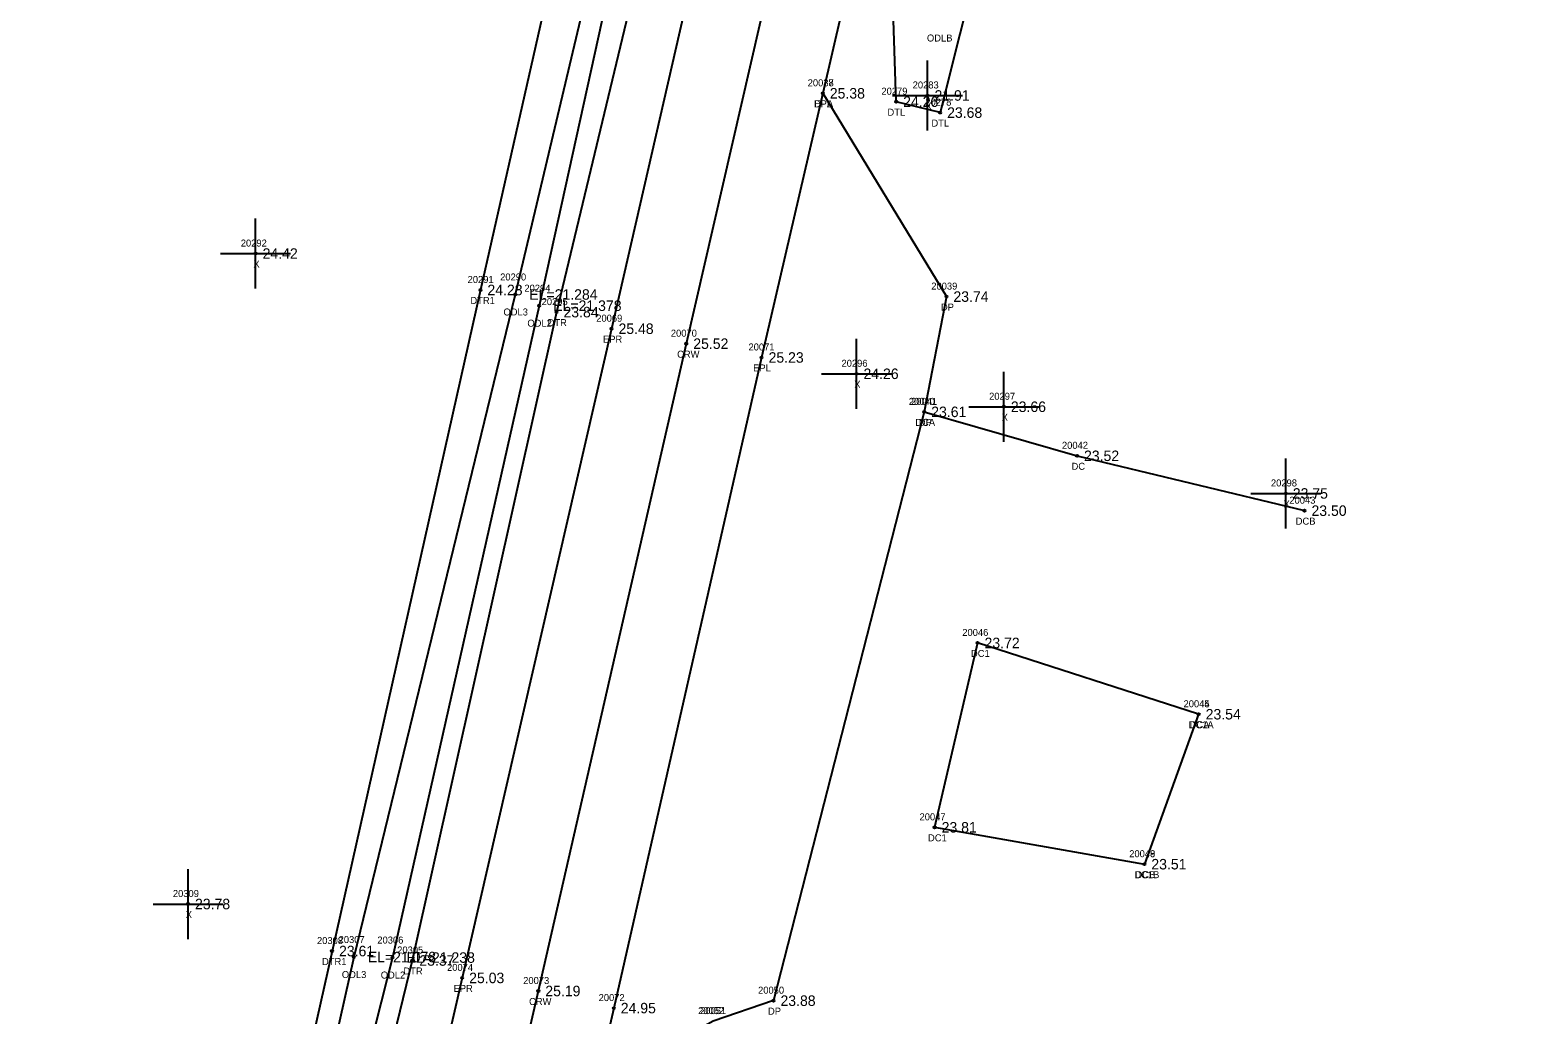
# Model space of a CAD drawing. Extents: x 2655177 to 2656219, y 761780 to 764748.
# Drawn here: x 2655847.5 to 2656062.9, y 764137.7 to 764278.4 of the extents above; entities that cross this region are included whole.
import ezdxf

# ---------------------------------------------------------------- set-up
doc = ezdxf.new("R2010")
doc.units = 0
for name, color, linetype in [('RD_DTM_BkLn1', 7, 'Continuous'), ('RD_EX_Conc', 7, 'Continuous'), ('RD_EX_Conc_txCode', 7, 'Continuous'), ('RD_EX_Driveway', 7, 'Continuous'), ('RD_EX_Driveway_txCode', 7, 'Continuous'), ('RD_EX_H2O', 7, 'Continuous'), ('RD_EX_H2O_txCode', 7, 'Continuous'), ('RD_EX_Misc', 7, 'Continuous'), ('RD_EX_Misc_txCode', 7, 'Continuous'), ('RD_EX_Road', 7, 'Continuous'), ('RD_EX_Road_txCode', 7, 'Continuous'), ('RD_EX_TX_Conc_ELEV', 7, 'Continuous'), ('RD_EX_TX_Driveway_ELEV', 7, 'Continuous'), ('RD_EX_TX_H2O_ELEV', 7, 'Continuous'), ('RD_EX_TX_Misc_ELEV', 7, 'Continuous'), ('RD_EX_TX_Road_ELEV', 7, 'Continuous'), ('RD_HC_Survey_ELEV', 7, 'Continuous'), ('RD_HC_Survey_txCode', 7, 'Continuous'), ('RD_SMD_Locator', 7, 'Continuous')]:
    doc.layers.add(name, color=color, linetype=linetype)

msp = doc.modelspace()

# ---------------------------------------------------------------- linework, layer by layer
at = {"layer": 'RD_DTM_BkLn1'}
msp.add_lwpolyline([(2656052.36, 764720.46), (2656029.22, 764619.66), (2656007.41, 764523.97), (2655985.61, 764427.64), (2655963.53, 764330.64), (2655941.2, 764233.56), (2655920.06, 764141.06), (2655898.52, 764047.86), (2655877.71, 763954.88), (2655855.89, 763859.81), (2655834.07, 763763.97), (2655811.81, 763666.79), (2655790.48, 763573.22), (2655769.27, 763483.63), (2655747.64, 763389.32), (2655725.4, 763293.96), (2655721.51, 763275.9)], dxfattribs=at)
at = {"layer": 'RD_EX_Conc'}
msp.add_line((2656014.41, 764180.61), (2656006.65, 764159.18), dxfattribs=at)
for points in [[(2655975.2, 764223.82), (2655997.03, 764217.54), (2656029.53, 764209.7)], [(2656014.41, 764180.61), (2655982.82, 764190.8), (2655976.69, 764164.45), (2656006.65, 764159.18)]]:
    msp.add_lwpolyline(points, dxfattribs=at)
at = {"layer": 'RD_EX_Driveway'}
msp.add_lwpolyline([(2655960.71, 764269.34), (2655978.37, 764240.29), (2655975.2, 764223.82), (2655953.66, 764139.68), (2655945.06, 764136.76), (2655937.53, 764132.52), (2655926.81, 764121.01)], dxfattribs=at)
at = {"layer": 'RD_EX_H2O'}
for points in [[(2655985.99, 764532.58), (2655990.84, 764527.53), (2655967.74, 764432.27), (2655946, 764335.4), (2655922.66, 764238.07), (2655902.06, 764145.42), (2655879.59, 764053.25), (2655859.1, 763959.14), (2655841.15, 763874.16), (2655837.57, 763865.39), (2655829.11, 763865.29), (2655761.29, 763886.78)], [(2655985.99, 764532.58), (2655980.45, 764530.42), (2655978.53, 764524.06), (2655957.73, 764434.81), (2655933.82, 764338.64), (2655911.79, 764241.24), (2655890.59, 764146.77), (2655869.91, 764054.39), (2655847.97, 763961.11)], [(2655986.13, 764527.03), (2655964.81, 764432.99), (2655941.76, 764337.09), (2655920.19, 764238.99), (2655899.24, 764145.84), (2655875.75, 764053.31), (2655856.78, 763959.16), (2655834.97, 763871.07)], [(2655983.66, 764527.79), (2655962.07, 764433.73), (2655939.64, 764337.32), (2655916.77, 764240.59), (2655893.69, 764145.91), (2655873.09, 764053.84), (2655852.96, 763960.1)], [(2656003.29, 764410.57), (2656005.26, 764401.05), (2655991.55, 764322.61), (2655977.47, 764266.58), (2655971.19, 764268.14), (2655970.76, 764281.2)]]:
    msp.add_lwpolyline(points, dxfattribs=at)
at = {"layer": 'RD_EX_Misc'}
for p, q in [((2655975.67, 764264.03), (2655975.67, 764274.03)), ((2655970.67, 764269.03), (2655980.67, 764269.03)), ((2655879.67, 764241.44), (2655879.67, 764251.44)), ((2655874.67, 764246.44), (2655884.67, 764246.44)), ((2655965.52, 764224.26), (2655965.52, 764234.26)), ((2655960.52, 764229.26), (2655970.52, 764229.26)), ((2655986.58, 764219.55), (2655986.58, 764229.55)), ((2655981.58, 764224.55), (2655991.58, 764224.55)), ((2656026.86, 764207.16), (2656026.86, 764217.16)), ((2656021.86, 764212.16), (2656031.86, 764212.16)), ((2655870.01, 764148.49), (2655870.01, 764158.49)), ((2655865.01, 764153.49), (2655875.01, 764153.49))]:
    msp.add_line(p, q, dxfattribs=at)
at = {"layer": 'RD_EX_Road'}
for points in [[(2656041.72, 764723.31), (2656018.5, 764622.03), (2656002.75, 764552.49), (2655997.43, 764530.02), (2655974.74, 764429.64), (2655952.97, 764333.57), (2655930.52, 764235.7), (2655909.18, 764142.93), (2655887.93, 764050.57), (2655866.91, 763957.26), (2655846.82, 763869.53), (2655845.21, 763862.22), (2655839.99, 763839.71), (2655823.38, 763766.66), (2655801.33, 763669.93), (2655780.03, 763576.53), (2655774.26, 763551.85), (2655771.37, 763539.86), (2655759.09, 763486.9), (2655736.94, 763391.72), (2655715.19, 763296.77), (2655711.35, 763278.45)], [(2656062.87, 764717.57), (2656039.84, 764617.04), (2656035.41, 764597.94), (2656033.38, 764589.18), (2656018.27, 764522.6), (2656017.22, 764517.64), (2656011.07, 764490.22), (2655996.52, 764425.63), (2655974.03, 764327.02), (2655960.71, 764269.34), (2655951.96, 764231.59), (2655930.84, 764138.62), (2655926.81, 764121.01)]]:
    msp.add_lwpolyline(points, dxfattribs=at)
at = {"layer": 'RD_SMD_Locator'}
for centre in [(2655960.71, 764269.34), (2655960.71, 764269.34), (2655971.19, 764268.14), (2655975.67, 764269.03), (2655977.47, 764266.58), (2655879.67, 764246.44), (2655911.79, 764241.24), (2655916.77, 764240.59), (2655978.37, 764240.29), (2655920.19, 764238.99), (2655922.66, 764238.07), (2655930.52, 764235.7), (2655941.2, 764233.56), (2655951.96, 764231.59), (2655965.52, 764229.26), (2655986.58, 764224.55), (2655975.2, 764223.82), (2655975.2, 764223.82), (2655997.03, 764217.54), (2656026.86, 764212.16), (2656029.53, 764209.7), (2655982.82, 764190.8), (2656014.41, 764180.61), (2656014.41, 764180.61), (2655976.69, 764164.45), (2656006.65, 764159.18), (2656006.65, 764159.18), (2655870.01, 764153.49), (2655890.59, 764146.77), (2655893.69, 764145.91), (2655899.24, 764145.84), (2655902.06, 764145.42), (2655909.18, 764142.93), (2655920.06, 764141.06), (2655930.84, 764138.62), (2655953.66, 764139.68)]:
    msp.add_circle(centre, 0.15, dxfattribs=at)

# ---------------------------------------------------------------- texts
at = {"layer": 'RD_EX_Conc_txCode'}
for s, p in [('20041', (2655973.32, 764224.82)), ('DCA', (2655973.93, 764221.82)), ('20042', (2655994.88, 764218.54)), ('DC', (2655996.25, 764215.54)), ('20043', (2656027.37, 764210.7)), ('DCB', (2656028.28, 764207.7)), ('20046', (2655980.64, 764191.8)), ('DC1', (2655981.88, 764188.8)), ('20044', (2656012.25, 764181.61)), ('20045', (2656012.25, 764181.61)), ('DC1A', (2656012.98, 764178.61)), ('DCA', (2656013.14, 764178.61)), ('20047', (2655974.53, 764165.45)), ('DC1', (2655975.74, 764162.45)), ('20048', (2656004.49, 764160.18)), ('20049', (2656004.49, 764160.18)), ('DC1B', (2656005.23, 764157.18)), ('DCB', (2656005.39, 764157.18)), ('20052', (2655942.9, 764137.76))]:
    msp.add_text(s, height=1, dxfattribs=at).set_placement(p)
at = {"layer": 'RD_EX_Driveway_txCode'}
for s, p in [('20038', (2655958.55, 764270.34)), ('DPA', (2655959.44, 764267.34)), ('20039', (2655976.21, 764241.29)), ('DP', (2655977.59, 764238.29)), ('20040', (2655973, 764224.82)), ('DP', (2655974.42, 764221.82)), ('20050', (2655951.46, 764140.68)), ('20051', (2655943.18, 764137.76)), ('DP', (2655952.88, 764137.68))]:
    msp.add_text(s, height=1, dxfattribs=at).set_placement(p)
at = {"layer": 'RD_EX_H2O_txCode'}
for s, p in [('ODLB', (2655975.59, 764276.74)), ('20279', (2655969.08, 764269.14)), ('20278', (2655975.36, 764267.58)), ('DTL', (2655969.95, 764266.14)), ('DTL', (2655976.23, 764264.58)), ('20291', (2655909.96, 764242.24)), ('20290', (2655914.61, 764242.59)), ('20294', (2655918.07, 764240.99)), ('DTR1', (2655910.36, 764239.24)), ('20295', (2655920.54, 764239.07)), ('ODL3', (2655915.08, 764237.59)), ('ODL2', (2655918.5, 764235.99)), ('DTR', (2655921.39, 764236.07)), ('20308', (2655888.44, 764147.77)), ('20307', (2655891.53, 764147.91)), ('20306', (2655897.06, 764147.84)), ('20305', (2655899.9, 764146.42)), ('DTR1', (2655889.16, 764144.77)), ('ODL3', (2655891.99, 764142.91)), ('ODL2', (2655897.55, 764142.84)), ('DTR', (2655900.79, 764143.42))]:
    msp.add_text(s, height=1, dxfattribs=at).set_placement(p)
at = {"layer": 'RD_EX_Misc_txCode'}
for s, p in [('20283', (2655973.55, 764270.03)), ('X', (2655975.36, 764267.03)), ('20292', (2655877.55, 764247.44)), ('X', (2655879.35, 764244.44)), ('20296', (2655963.38, 764230.26)), ('X', (2655965.2, 764227.26)), ('20297', (2655984.47, 764225.55)), ('X', (2655986.27, 764222.55)), ('20298', (2656024.74, 764213.16)), ('X', (2656026.54, 764210.16)), ('20309', (2655867.85, 764154.49)), ('X', (2655869.69, 764151.49))]:
    msp.add_text(s, height=1, dxfattribs=at).set_placement(p)
at = {"layer": 'RD_EX_Road_txCode'}
for s, p in [('20037', (2655958.55, 764270.34)), ('EPL', (2655959.51, 764267.34)), ('20069', (2655928.34, 764236.7)), ('EPR', (2655929.3, 764233.7)), ('20071', (2655950.09, 764232.59)), ('EPL', (2655950.76, 764229.59)), ('20074', (2655907.02, 764143.93)), ('EPR', (2655907.95, 764140.93)), ('20072', (2655928.68, 764139.62))]:
    msp.add_text(s, height=1, dxfattribs=at).set_placement(p)
at = {"layer": 'RD_EX_TX_Conc_ELEV'}
for s, p in [('23.61', (2655976.2, 764223.07)), ('23.52', (2655998.03, 764216.79)), ('23.50', (2656030.53, 764208.95)), ('23.72', (2655983.82, 764190.05)), ('23.54', (2656015.41, 764179.86)), ('23.54', (2656015.41, 764179.86)), ('23.81', (2655977.69, 764163.7)), ('23.51', (2656007.65, 764158.43)), ('23.51', (2656007.65, 764158.43))]:
    msp.add_text(s, height=1.5, dxfattribs=at).set_placement(p)
at = {"layer": 'RD_EX_TX_Driveway_ELEV'}
for s, p in [('25.38', (2655961.71, 764268.59)), ('23.74', (2655979.37, 764239.54)), ('23.61', (2655976.2, 764223.07)), ('23.88', (2655954.66, 764138.93))]:
    msp.add_text(s, height=1.5, dxfattribs=at).set_placement(p)
at = {"layer": 'RD_EX_TX_H2O_ELEV'}
for s, p in [('24.26', (2655972.19, 764267.39)), ('23.68', (2655978.47, 764265.83)), ('24.28', (2655912.79, 764240.49)), ('EL=21.284', (2655918.77, 764239.84)), ('EL=21.378', (2655922.19, 764238.24)), ('23.84', (2655923.66, 764237.32)), ('23.61', (2655891.59, 764146.02)), ('EL=21.078', (2655895.69, 764145.16)), ('EL=21.238', (2655901.24, 764145.09)), ('23.37', (2655903.06, 764144.67))]:
    msp.add_text(s, height=1.5, dxfattribs=at).set_placement(p)
at = {"layer": 'RD_EX_TX_Misc_ELEV'}
for s, p in [('21.91', (2655976.67, 764268.28)), ('24.42', (2655880.67, 764245.69)), ('24.26', (2655966.52, 764228.51)), ('23.66', (2655987.58, 764223.8)), ('23.75', (2656027.86, 764211.41)), ('23.78', (2655871.01, 764152.74))]:
    msp.add_text(s, height=1.5, dxfattribs=at).set_placement(p)
at = {"layer": 'RD_EX_TX_Road_ELEV'}
for s, p in [('25.38', (2655961.71, 764268.59)), ('25.48', (2655931.52, 764234.95)), ('25.23', (2655952.96, 764230.84)), ('25.03', (2655910.18, 764142.18)), ('24.95', (2655931.84, 764137.87))]:
    msp.add_text(s, height=1.5, dxfattribs=at).set_placement(p)
at = {"layer": 'RD_HC_Survey_ELEV'}
for s, p in [('25.52', (2655942.2, 764232.81)), ('25.19', (2655921.06, 764140.31))]:
    msp.add_text(s, height=1.5, dxfattribs=at).set_placement(p)
at = {"layer": 'RD_HC_Survey_txCode'}
for s, p in [('20070', (2655939, 764234.56)), ('CRW', (2655939.89, 764231.56)), ('20073', (2655917.9, 764142.06)), ('CRW', (2655918.74, 764139.06))]:
    msp.add_text(s, height=1, dxfattribs=at).set_placement(p)

doc.saveas('drawing.dxf')
